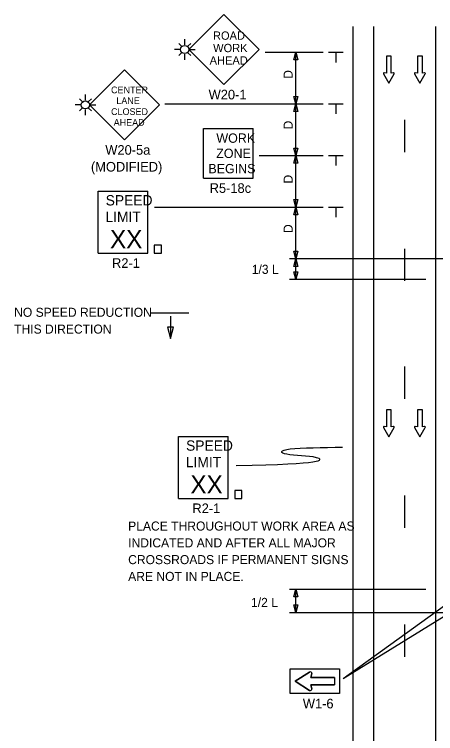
# Model space of a CAD drawing. Extents: x 16525 to 18478, y 5730 to 6927.
# Drawn here: x 16750 to 17076, y 6370 to 6927 of the extents above; entities that cross this region are included whole.
import ezdxf

# ---------------------------------------------------------------- set-up
doc = ezdxf.new("R2010")
doc.units = 0
for name, color, linetype in [('ALI_LEGAL_EX', 7, 'Continuous'), ('MT_SCRATCH_LEVEL_E', 7, 'Continuous'), ('PAVT_EDGE_EX', 7, 'Continuous'), ('TRAFFIC_SIGNS_PR', 7, 'Continuous'), ('TYPICAL_TEXT_DIMEN_PR', 7, 'Continuous')]:
    doc.layers.add(name, color=color, linetype=linetype)

msp = doc.modelspace()

# ---------------------------------------------------------------- linework, layer by layer
at = {"layer": 'ALI_LEGAL_EX'}
for points in [[(17051.59, 6845.22), (17051.59, 6820.22)], [(17051.59, 6745.22), (17051.59, 6720.56)], [(17051.59, 6654.22), (17051.59, 6629.22)], [(17051.59, 6554.22), (17051.59, 6529.22)], [(17051.59, 6454.22), (17051.59, 6429.22)]]:
    msp.add_lwpolyline(points, dxfattribs=at)
at = {"layer": 'MT_SCRATCH_LEVEL_E'}
for p, q in [((17041.26, 6894.53), (17037.52, 6894.53)), ((17037.52, 6894.53), (17037.52, 6881.27)), ((17041.26, 6894.53), (17037.52, 6894.53)), ((17037.52, 6894.53), (17037.52, 6881.27)), ((17041.26, 6881.27), (17041.26, 6894.53)), ((17041.26, 6881.27), (17041.26, 6894.53)), ((17065.33, 6894.53), (17061.59, 6894.53)), ((17061.59, 6894.53), (17061.59, 6881.27)), ((17065.33, 6894.53), (17061.59, 6894.53)), ((17061.59, 6894.53), (17061.59, 6881.27)), ((17065.33, 6881.27), (17065.33, 6894.53)), ((17065.33, 6881.27), (17065.33, 6894.53)), ((17035.26, 6880.9), (17039.41, 6873.66)), ((17035.26, 6880.9), (17039.41, 6873.66)), ((17037.52, 6881.27), (17035.74, 6881.59)), ((17037.52, 6881.27), (17035.74, 6881.59)), ((17039.41, 6873.66), (17043.52, 6880.9)), ((17039.41, 6873.66), (17043.52, 6880.9)), ((17043.03, 6881.59), (17041.26, 6881.27)), ((17043.03, 6881.59), (17041.26, 6881.27)), ((17059.33, 6880.9), (17063.48, 6873.66)), ((17059.33, 6880.9), (17063.48, 6873.66)), ((17061.59, 6881.27), (17059.81, 6881.59)), ((17061.59, 6881.27), (17059.81, 6881.59)), ((17063.48, 6873.66), (17067.59, 6880.9)), ((17063.48, 6873.66), (17067.59, 6880.9)), ((17067.11, 6881.59), (17065.33, 6881.27)), ((17067.11, 6881.59), (17065.33, 6881.27)), ((17041.26, 6620.66), (17037.52, 6620.66)), ((17037.52, 6620.66), (17037.52, 6607.4)), ((17041.26, 6620.66), (17037.52, 6620.66)), ((17037.52, 6620.66), (17037.52, 6607.4)), ((17041.26, 6607.4), (17041.26, 6620.66)), ((17041.26, 6607.4), (17041.26, 6620.66)), ((17065.33, 6620.66), (17061.59, 6620.66)), ((17061.59, 6620.66), (17061.59, 6607.4)), ((17065.33, 6620.66), (17061.59, 6620.66)), ((17061.59, 6620.66), (17061.59, 6607.4)), ((17065.33, 6607.4), (17065.33, 6620.66)), ((17065.33, 6607.4), (17065.33, 6620.66)), ((17035.26, 6607.03), (17039.41, 6599.79)), ((17035.26, 6607.03), (17039.41, 6599.79)), ((17037.52, 6607.4), (17035.74, 6607.72)), ((17037.52, 6607.4), (17035.74, 6607.72)), ((17039.41, 6599.79), (17043.52, 6607.03)), ((17039.41, 6599.79), (17043.52, 6607.03)), ((17043.03, 6607.72), (17041.26, 6607.4)), ((17043.03, 6607.72), (17041.26, 6607.4)), ((17059.33, 6607.03), (17063.48, 6599.79)), ((17059.33, 6607.03), (17063.48, 6599.79)), ((17061.59, 6607.4), (17059.81, 6607.72)), ((17061.59, 6607.4), (17059.81, 6607.72)), ((17063.48, 6599.79), (17067.59, 6607.03)), ((17063.48, 6599.79), (17067.59, 6607.03)), ((17067.11, 6607.72), (17065.33, 6607.4)), ((17067.11, 6607.72), (17065.33, 6607.4))]:
    msp.add_line(p, q, dxfattribs=at)
for centre, start, end in [((17035.67, 6881.13), 80.0362, 209.7731), ((17035.67, 6881.13), 80.0362, 209.7731), ((17043.11, 6881.13), 330.4248, 99.9638), ((17043.11, 6881.13), 330.4248, 99.9638), ((17059.74, 6881.13), 80.0362, 209.7731), ((17059.74, 6881.13), 80.0362, 209.7731), ((17067.18, 6881.13), 330.4248, 99.9638), ((17067.18, 6881.13), 330.4248, 99.9638), ((17035.67, 6607.26), 80.0362, 209.7731), ((17035.67, 6607.26), 80.0362, 209.7731), ((17043.11, 6607.26), 330.4248, 99.9638), ((17043.11, 6607.26), 330.4248, 99.9638), ((17059.74, 6607.26), 80.0362, 209.7731), ((17059.74, 6607.26), 80.0362, 209.7731), ((17067.18, 6607.26), 330.4248, 99.9638), ((17067.18, 6607.26), 330.4248, 99.9638)]:
    msp.add_arc(centre, 0.463, start, end, dxfattribs=at)
at = {"layer": 'PAVT_EDGE_EX'}
for p, q in [((17011.59, 6917.57), (17011.59, 6063.18)), ((17027.59, 6917.57), (17027.59, 6063.18)), ((17075.59, 6917.57), (17075.59, 6063.18))]:
    msp.add_line(p, q, dxfattribs=at)
at = {"layer": 'TRAFFIC_SIGNS_PR'}
for p, q in [((16911.72, 6926.82), (16884.53, 6899.64)), ((16938.9, 6899.64), (16911.72, 6926.82)), ((16881.38, 6903.19), (16881.38, 6907.69)), ((16878.86, 6902.15), (16876.76, 6904.26)), ((16883.89, 6902.15), (16886, 6904.26)), ((16878.22, 6899.64), (16873.39, 6899.64)), ((16878.86, 6897.12), (16876.76, 6895.02)), ((16881.38, 6891.67), (16881.38, 6896.08)), ((16883.89, 6897.12), (16886, 6895.02)), ((16884.53, 6899.64), (16911.72, 6872.45)), ((16884.53, 6899.64), (16889.41, 6899.64)), ((16911.72, 6872.45), (16938.9, 6899.64)), ((16834.77, 6883.88), (16807.62, 6856.73)), ((16861.92, 6856.73), (16834.77, 6883.88)), ((16804.47, 6860.28), (16804.47, 6864.79)), ((16801.31, 6856.73), (16796.47, 6856.73)), ((16801.95, 6859.24), (16799.84, 6861.35)), ((16806.98, 6859.24), (16809.09, 6861.35)), ((16807.62, 6856.73), (16812.5, 6856.73)), ((16807.62, 6856.73), (16834.77, 6829.58)), ((16834.77, 6829.58), (16861.92, 6856.73)), ((16801.95, 6854.22), (16799.84, 6852.11)), ((16804.47, 6848.76), (16804.47, 6853.18)), ((16806.98, 6854.22), (16809.09, 6852.11)), ((16895.87, 6800.03), (16895.87, 6838.43)), ((16895.87, 6838.43), (16934.27, 6838.43)), ((16934.27, 6800.03), (16934.27, 6838.43)), ((16895.87, 6800.03), (16934.27, 6800.03)), ((16814.42, 6789.98), (16852.82, 6789.98)), ((16814.42, 6741.98), (16814.42, 6789.98)), ((16852.82, 6741.98), (16852.82, 6789.98)), ((16814.42, 6741.98), (16852.82, 6741.98)), ((16876.65, 6600.05), (16915.05, 6600.05)), ((16876.65, 6552.05), (16876.65, 6600.05)), ((16915.05, 6552.05), (16915.05, 6600.05)), ((16876.65, 6552.05), (16915.05, 6552.05)), ((16978.04, 6417.53), (16966.88, 6410.42)), ((16978.88, 6413.22), (16979.72, 6416.28)), ((16997.28, 6413.22), (16978.88, 6413.22)), ((16997.28, 6413.22), (16997.28, 6407.62)), ((16966.88, 6410.42), (16978.04, 6403.32)), ((16979.72, 6404.56), (16978.88, 6407.62)), ((16978.88, 6407.62), (16997.28, 6407.62))]:
    msp.add_line(p, q, dxfattribs=at)
for points in [[(16857.84, 6741.98), (16863.43, 6741.98), (16863.43, 6748.15), (16857.84, 6748.15)], [(16920.07, 6552.05), (16925.66, 6552.05), (16925.66, 6558.22), (16920.07, 6558.22)], [(17001.28, 6400.82), (16962.88, 6400.82), (16962.88, 6420.02), (17001.28, 6420.02)]]:
    msp.add_lwpolyline(points, close=True, dxfattribs=at)
for points in [[(16978.04, 6403.32), (16966.88, 6410.42), (16978.04, 6417.53)], [(16979.72, 6416.28), (16978.88, 6413.22), (16997.28, 6413.22), (16997.28, 6407.62), (16978.88, 6407.62), (16979.72, 6404.56)]]:
    msp.add_lwpolyline(points, dxfattribs=at)
for centre in [(16881.38, 6899.64), (16804.46, 6856.73)]:
    msp.add_circle(centre, 3.15, dxfattribs=at)
for centre, start, end in [((16978.64, 6416.58), 344.6731, 122.4696), ((16978.64, 6416.58), 344.6731, 122.4696), ((16978.64, 6404.27), 237.5304, 15.3269), ((16978.64, 6404.27), 237.5304, 15.3269)]:
    msp.add_arc(centre, 1.12, start, end, dxfattribs=at)
at = {"layer": 'TYPICAL_TEXT_DIMEN_PR'}
for p, q in [((16943.76, 6897.47), (16988.49, 6897.47)), ((16965.92, 6891.61), (16967.49, 6897.47)), ((16967.49, 6897.47), (16969.06, 6891.61)), ((16967.49, 6857.47), (16967.49, 6897.47)), ((16992.74, 6897.47), (17003.99, 6897.47)), ((16998.37, 6897.47), (16998.37, 6889.69)), ((16967.49, 6891.61), (16965.92, 6891.61)), ((16969.06, 6891.61), (16967.49, 6891.61)), ((16967.49, 6857.47), (16965.92, 6863.34)), ((16965.92, 6863.34), (16967.49, 6863.34)), ((16967.49, 6863.34), (16969.06, 6863.34)), ((16969.06, 6863.34), (16967.49, 6857.47)), ((16866.01, 6857.47), (16988.49, 6857.47)), ((16965.92, 6851.61), (16967.49, 6857.47)), ((16967.49, 6817.47), (16967.49, 6857.47)), ((16967.49, 6857.47), (16969.06, 6851.61)), ((16992.74, 6857.47), (17003.99, 6857.47)), ((16998.37, 6857.47), (16998.37, 6849.69)), ((16967.49, 6851.61), (16965.92, 6851.61)), ((16969.06, 6851.61), (16967.49, 6851.61)), ((16967.49, 6817.47), (16965.92, 6823.34)), ((16965.92, 6823.34), (16967.49, 6823.34)), ((16967.49, 6823.34), (16969.06, 6823.34)), ((16969.06, 6823.34), (16967.49, 6817.47)), ((16938.9, 6817.47), (16988.49, 6817.47)), ((16965.92, 6811.61), (16967.49, 6817.47)), ((16967.49, 6817.47), (16969.06, 6811.61)), ((16967.49, 6777.47), (16967.49, 6817.47)), ((16992.74, 6817.47), (17003.99, 6817.47)), ((16998.37, 6817.47), (16998.37, 6809.69)), ((16967.49, 6811.61), (16965.92, 6811.61)), ((16969.06, 6811.61), (16967.49, 6811.61)), ((16967.49, 6777.47), (16965.92, 6783.34)), ((16965.92, 6783.34), (16967.49, 6783.34)), ((16967.49, 6783.34), (16969.06, 6783.34)), ((16969.06, 6783.34), (16967.49, 6777.47)), ((16857.91, 6777.47), (16988.49, 6777.47)), ((16965.92, 6771.61), (16967.49, 6777.47)), ((16967.49, 6777.47), (16969.06, 6771.61)), ((16967.49, 6737.47), (16967.49, 6777.47)), ((16992.74, 6777.47), (17003.99, 6777.47)), ((16998.37, 6777.47), (16998.37, 6769.69)), ((16967.49, 6771.61), (16965.92, 6771.61)), ((16969.06, 6771.61), (16967.49, 6771.61)), ((16967.49, 6737.47), (16965.92, 6743.34)), ((16965.92, 6743.34), (16967.49, 6743.34)), ((16967.49, 6743.34), (16969.06, 6743.34)), ((16969.06, 6743.34), (16967.49, 6737.47)), ((17092.68, 6737.47), (16962.49, 6737.47)), ((16965.92, 6731.61), (16967.49, 6737.47)), ((16967.49, 6721.71), (16967.49, 6737.47)), ((16967.49, 6737.47), (16969.06, 6731.61)), ((16967.49, 6731.61), (16965.92, 6731.61)), ((16969.06, 6731.61), (16967.49, 6731.61)), ((16967.49, 6721.71), (16965.92, 6727.57)), ((16965.92, 6727.57), (16967.49, 6727.57)), ((16967.49, 6727.57), (16969.06, 6727.57)), ((16969.06, 6727.57), (16967.49, 6721.71)), ((16962.49, 6721.72), (17068.12, 6721.72)), ((16884.47, 6695.5), (16855.03, 6695.5)), ((16870.29, 6693), (16870.29, 6675.88)), ((16870.29, 6684.67), (16867.94, 6684.67)), ((16867.94, 6684.67), (16870.29, 6675.88)), ((16870.29, 6675.88), (16872.65, 6684.67)), ((16872.65, 6684.67), (16870.29, 6684.67)), ((16962.49, 6481.72), (17068.12, 6481.72)), ((16965.92, 6475.86), (16967.49, 6481.72)), ((16967.49, 6463.75), (16967.49, 6481.72)), ((16967.49, 6481.72), (16969.06, 6475.86)), ((17003.97, 6412.5), (17096.17, 6479.01)), ((16967.49, 6475.86), (16965.92, 6475.86)), ((16969.06, 6475.86), (16967.49, 6475.86)), ((17003.97, 6412.5), (17102.79, 6473.5)), ((16967.49, 6463.75), (16965.92, 6469.61)), ((16965.92, 6469.61), (16967.49, 6469.61)), ((16967.49, 6469.61), (16969.06, 6469.61)), ((16969.06, 6469.61), (16967.49, 6463.75)), ((16962.49, 6463.75), (17092.12, 6463.75))]:
    msp.add_line(p, q, dxfattribs=at)
msp.add_open_spline([(16921.28, 6577.42), (16990.55, 6578.66), (16988.56, 6585.16), (16954.79, 6585.16), (16954.79, 6591.31), (16988.13, 6591.31), (17003.59, 6591.76)], degree=3, dxfattribs=at)

# ---------------------------------------------------------------- texts
at = {"layer": 'TRAFFIC_SIGNS_PR'}
for s, height, p in [('ROAD', 6.408, (16903.25, 6907.18)), ('WORK', 6.408, (16903.36, 6897.57)), ('AHEAD', 6.408, (16900.66, 6887.96)), ('CENTER', 5.2, (16824.35, 6865.73)), ('W20-1', 7.449, (16899.87, 6861)), ('LANE', 5.2, (16828.42, 6857.33)), ('CLOSED', 5.2, (16824.35, 6848.93)), ('AHEAD', 5.2, (16826.38, 6840.53)), ('WORK', 7.217, (16905.87, 6827.4)), ('W20-5a', 7.44, (16819.91, 6818.14)), ('ZONE', 7.217, (16905.75, 6815.59)), ('(MODIFIED)', 7.44, (16808.77, 6805.1)), ('BEGINS', 7.217, (16899.68, 6803.78)), ('R5-18c', 7.44, (16900.68, 6788.59)), ('SPEED', 8, (16820.19, 6778.84)), ('LIMIT', 8, (16820.03, 6766.04)), ('XX', 14.031, (16823.54, 6745.73)), ('R2-1', 7.44, (16825.1, 6730.53)), ('SPEED', 8, (16882.42, 6588.91)), ('LIMIT', 8, (16882.26, 6576.11)), ('XX', 14.031, (16885.77, 6555.81)), ('R2-1', 7.44, (16887.33, 6540.61)), ('PLACE THROUGHOUT WORK AREA AS', 7, (16837.58, 6527.09)), ('INDICATED AND AFTER ALL MAJOR', 7, (16837.58, 6514.09)), ('CROSSROADS IF PERMANENT SIGNS', 7, (16837.58, 6501.09)), ('ARE NOT IN PLACE.', 7, (16837.58, 6488.09)), ('W1-6', 7.44, (16972.82, 6389.38))]:
    msp.add_text(s, height=height, dxfattribs=at).set_placement(p)
at = {"layer": 'TYPICAL_TEXT_DIMEN_PR'}
for p in [(16964.93, 6876.93), (16964.93, 6837.75), (16964.93, 6795.84), (16964.93, 6757.5)]:
    msp.add_text('D', height=7, rotation=90, dxfattribs=at).set_placement(p)
for s, p in [('1/3 L', (16933.25, 6725.89)), ('NO SPEED REDUCTION', (16749.31, 6692.62)), ('THIS DIRECTION', (16749.31, 6679.62)), ('1/2 L', (16932.69, 6467.94))]:
    msp.add_text(s, height=7, dxfattribs=at).set_placement(p)

doc.saveas('drawing.dxf')
